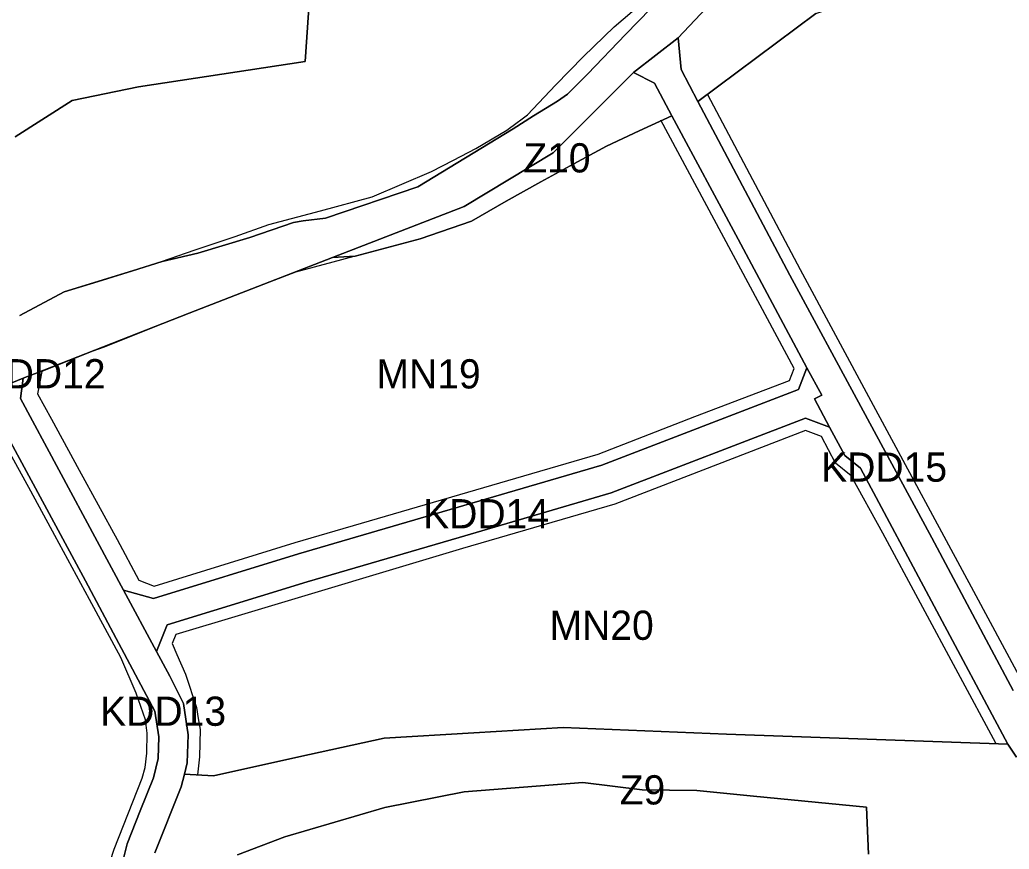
# Model space of a CAD drawing. Extents: x 7428841 to 7433518, y 5545054 to 5546840.
# Drawn here: x 7430323 to 7430661.7, y 5545549.4 to 5545833.3 of the extents above; entities that cross this region are included whole.
import ezdxf

# ---------------------------------------------------------------- set-up
doc = ezdxf.new("R2010")
doc.units = 0
for name, color, linetype in [('linie_rozgraniczajace', 7, 'Continuous'), ('linie_zabudowy_nieprzekraczalne', 7, 'Continuous'), ('oznaczenia_przeznaczen', 7, 'Continuous')]:
    doc.layers.add(name, color=color, linetype=linetype)

msp = doc.modelspace()

# ---------------------------------------------------------------- linework, layer by layer
at = {"layer": 'linie_rozgraniczajace'}
for points in [[(7430663.1, 5545603.69), (7430635.16, 5545655.99), (7430586.55, 5545745.89), (7430555.14, 5545805.32), (7430595.45, 5545835.45), (7430635.56, 5545849.06), (7430627.71, 5545865.6), (7430632.95, 5545868.01), (7430642.11, 5545873.01), (7430651.28, 5545878), (7430675.25, 5545892.35)], [(7430569.32, 5545849.46), (7430548.34, 5545827.05), (7430540.7, 5545821.15), (7430533.06, 5545815.25), (7430505.57, 5545787.69), (7430475.12, 5545769.42), (7430430.05, 5545751.94), (7430380.93, 5545732.82), (7430328.04, 5545712.13), (7430324.14, 5545710.6), (7430320.24, 5545709.08)], [(7430595.45, 5545835.45), (7430555.14, 5545805.32), (7430549.37, 5545816.25), (7430548.34, 5545827.05), (7430569.32, 5545849.46)], [(7430321.42, 5545793.16), (7430340.97, 5545805.64), (7430363.66, 5545810.3), (7430420.71, 5545819.01), (7430422.45, 5545844.1)], [(7430422.45, 5545844.1), (7430420.71, 5545819.01), (7430363.66, 5545810.3), (7430340.97, 5545805.64), (7430321.42, 5545793.16)], [(7430322.99, 5545732.04), (7430338.17, 5545740.16), (7430361.53, 5545747.33), (7430371.7, 5545750.49), (7430383.92, 5545753.38), (7430401.78, 5545758.72), (7430416.65, 5545763.91), (7430420.04, 5545764.49), (7430427.68, 5545765.38), (7430459.23, 5545776.13), (7430491.84, 5545795.96), (7430498.85, 5545800.42), (7430507.04, 5545805.4), (7430510.44, 5545807.79), (7430517.4, 5545814.73), (7430530.39, 5545828.27), (7430538.96, 5545837.09)], [(7430538.96, 5545837.09), (7430530.39, 5545828.27), (7430517.4, 5545814.73), (7430510.44, 5545807.79), (7430507.04, 5545805.4), (7430498.85, 5545800.42), (7430491.84, 5545795.96), (7430459.23, 5545776.13), (7430427.68, 5545765.38), (7430420.04, 5545764.49), (7430416.65, 5545763.91), (7430401.78, 5545758.72), (7430383.92, 5545753.38), (7430371.7, 5545750.49), (7430361.53, 5545747.33), (7430338.17, 5545740.16), (7430322.99, 5545732.04)], [(7430664.22, 5545580.93), (7430661.23, 5545585.41), (7430610.78, 5545679.77), (7430605.4, 5545684.16), (7430600.22, 5545693.85), (7430595.05, 5545703.55), (7430597.5, 5545704.75), (7430592.46, 5545714.16), (7430568.88, 5545758.14), (7430546.21, 5545800.44), (7430540.26, 5545811.53), (7430533.06, 5545815.25), (7430540.7, 5545821.15), (7430548.34, 5545827.05), (7430549.37, 5545816.25), (7430555.14, 5545805.32), (7430586.55, 5545745.89), (7430635.16, 5545655.99), (7430663.1, 5545603.69)], [(7430356.4, 5545538.02), (7430359.72, 5545551.27), (7430364.23, 5545562.59), (7430368.74, 5545573.91), (7430370.39, 5545580.44), (7430370.65, 5545587.94), (7430369.28, 5545596.66), (7430345.47, 5545641.25), (7430316.75, 5545694.49), (7430313.95, 5545699.78), (7430307.55, 5545703.17), (7430320.24, 5545709.08), (7430324.14, 5545710.6), (7430323.19, 5545703.65), (7430349.47, 5545654.88), (7430358.51, 5545638.06), (7430369.81, 5545617.05), (7430374.39, 5545608.67), (7430378.99, 5545599.31), (7430380.68, 5545588.55), (7430380.35, 5545579.03), (7430379.33, 5545575.09), (7430378.27, 5545570.82), (7430369.25, 5545548.19)], [(7430229.77, 5545546.84), (7430211.33, 5545566.73), (7430187.12, 5545592.88), (7430159.46, 5545623.96), (7430159.13, 5545632.06), (7430161.15, 5545634.58), (7430188, 5545647.19), (7430214.85, 5545659.79), (7430268.56, 5545685.01), (7430307.55, 5545703.17), (7430313.95, 5545699.78), (7430316.75, 5545694.49), (7430345.47, 5545641.25), (7430369.28, 5545596.66), (7430370.65, 5545587.94), (7430370.39, 5545580.44), (7430368.74, 5545573.91), (7430364.23, 5545562.59), (7430359.72, 5545551.27), (7430356.4, 5545538.02)], [(7430369.25, 5545548.19), (7430378.27, 5545570.82), (7430379.33, 5545575.09), (7430389.29, 5545574.54), (7430418.51, 5545581), (7430447.74, 5545587.45), (7430478.37, 5545589.24), (7430509.01, 5545591.03), (7430564.93, 5545588.74), (7430661.23, 5545585.41), (7430664.22, 5545580.93)], [(7430397.54, 5545547.49), (7430413.69, 5545553.71), (7430447.96, 5545563.72), (7430475.07, 5545569.11), (7430495.4, 5545570.66), (7430515.74, 5545572.22), (7430525.89, 5545570.98), (7430536.05, 5545569.74), (7430545.4, 5545569.61), (7430554.75, 5545569.48), (7430574.15, 5545567.59), (7430612.89, 5545563.81), (7430613.58, 5545547.7)], [(7430613.58, 5545547.7), (7430612.89, 5545563.81), (7430574.15, 5545567.59), (7430554.75, 5545569.48), (7430545.4, 5545569.61), (7430536.05, 5545569.74), (7430525.89, 5545570.98), (7430515.74, 5545572.22), (7430495.4, 5545570.66), (7430475.07, 5545569.11), (7430447.96, 5545563.72), (7430413.69, 5545553.71), (7430397.54, 5545547.49)]]:
    msp.add_lwpolyline(points, dxfattribs=at)
for points in [[(7430430.05, 5545751.94), (7430475.12, 5545769.42), (7430505.57, 5545787.69), (7430533.06, 5545815.25), (7430540.26, 5545811.53), (7430546.21, 5545800.44), (7430535.05, 5545795.23), (7430523.89, 5545790.02), (7430512.61, 5545783.93), (7430501.32, 5545777.84), (7430489.53, 5545771.19), (7430477.62, 5545764.37), (7430460.11, 5545758.29), (7430437.82, 5545752.38)], [(7430323.19, 5545703.65), (7430324.14, 5545710.6), (7430328.04, 5545712.13), (7430380.93, 5545732.82), (7430430.05, 5545751.94), (7430437.82, 5545752.38), (7430460.11, 5545758.29), (7430477.62, 5545764.37), (7430489.53, 5545771.19), (7430501.32, 5545777.84), (7430512.61, 5545783.93), (7430523.89, 5545790.02), (7430535.05, 5545795.23), (7430546.21, 5545800.44), (7430568.88, 5545758.14), (7430592.46, 5545714.16), (7430589.53, 5545706.78), (7430522.26, 5545680.81), (7430470.35, 5545665.66), (7430418.45, 5545650.52), (7430368.81, 5545635.24), (7430358.51, 5545638.06), (7430349.47, 5545654.88)], [(7430358.51, 5545638.06), (7430368.81, 5545635.24), (7430418.45, 5545650.52), (7430470.35, 5545665.66), (7430522.26, 5545680.81), (7430589.53, 5545706.78), (7430592.46, 5545714.16), (7430597.5, 5545704.75), (7430595.05, 5545703.55), (7430600.22, 5545693.85), (7430591.94, 5545696.99), (7430525.47, 5545671.33), (7430473.39, 5545656.13), (7430421.32, 5545640.94), (7430373.44, 5545626.2), (7430369.81, 5545617.05)], [(7430369.81, 5545617.05), (7430373.44, 5545626.2), (7430421.32, 5545640.94), (7430473.39, 5545656.13), (7430525.47, 5545671.33), (7430591.94, 5545696.99), (7430600.22, 5545693.85), (7430605.4, 5545684.16), (7430610.78, 5545679.77), (7430661.23, 5545585.41), (7430564.93, 5545588.74), (7430509.01, 5545591.03), (7430478.37, 5545589.24), (7430447.74, 5545587.45), (7430418.51, 5545581), (7430389.29, 5545574.54), (7430379.33, 5545575.09), (7430380.35, 5545579.03), (7430380.68, 5545588.55), (7430378.99, 5545599.31), (7430374.39, 5545608.67)]]:
    msp.add_lwpolyline(points, close=True, dxfattribs=at)
at = {"layer": 'linie_zabudowy_nieprzekraczalne'}
for points in [[(7430322.99, 5545732.04), (7430338.17, 5545740.16), (7430349.85, 5545743.75), (7430361.53, 5545747.33), (7430371.52, 5545750.51), (7430383.04, 5545754.49), (7430396.69, 5545759.12), (7430408.25, 5545763.16), (7430425.96, 5545767.9), (7430443.67, 5545772.63), (7430463.9, 5545781.4), (7430471.51, 5545785.28), (7430479.11, 5545789.16), (7430489.75, 5545795.47), (7430493.25, 5545798.12), (7430494.48, 5545799.04), (7430496.78, 5545800.75), (7430506.43, 5545810.85), (7430515.94, 5545820.7), (7430526.43, 5545830.89), (7430538.8, 5545841.5), (7430541.3, 5545843.63), (7430544.56, 5545846.49)], [(7430558.4, 5545807.72), (7430590.08, 5545747.77), (7430614.37, 5545702.84), (7430650.25, 5545636.23), (7430669.09, 5545601.23), (7430677.86, 5545585.93)], [(7430588.05, 5545713.92), (7430542.48, 5545798.92)], [(7430437.4, 5545752.23), (7430430.11, 5545750.3), (7430417.35, 5545746.94), (7430405.49, 5545742.38), (7430380.93, 5545732.82), (7430351.5, 5545721.08), (7430348.01, 5545719.91), (7430330.83, 5545713.03)], [(7430330.53, 5545712.91), (7430329.08, 5545705.25), (7430333.85, 5545696.57), (7430343.31, 5545679.1), (7430356.38, 5545655.43), (7430363.76, 5545641.51)], [(7430363.76, 5545641.51), (7430368.97, 5545639.47), (7430417.3, 5545654.35), (7430520.97, 5545684.6), (7430554.1, 5545697.46), (7430586.46, 5545709.88), (7430588.05, 5545713.92)], [(7430352.62, 5545523.31), (7430351.71, 5545527.21), (7430351.75, 5545535.04), (7430352.52, 5545541), (7430355.29, 5545549.4), (7430364.94, 5545573.76), (7430365.95, 5545577.43), (7430366.53, 5545582.28), (7430366.66, 5545589.17), (7430365.98, 5545593.7), (7430362.88, 5545602.83), (7430357.63, 5545614.99), (7430346.86, 5545634.84), (7430334.97, 5545656.8), (7430326.8, 5545671.95), (7430319.76, 5545684.81), (7430313.72, 5545695.75), (7430303.88, 5545701.34)], [(7430597.39, 5545690.67), (7430591.95, 5545692.71), (7430526.75, 5545667.54), (7430474.53, 5545652.3), (7430398.94, 5545629.66), (7430376.45, 5545622.92), (7430375.18, 5545619.8)], [(7430657.1, 5545585.71), (7430618.4, 5545657.59), (7430607.65, 5545677.16), (7430602.25, 5545681.56), (7430597.39, 5545690.67)], [(7430375.18, 5545619.8), (7430376.76, 5545616.08), (7430379.69, 5545609.3), (7430383.54, 5545597.97), (7430384.11, 5545594.16), (7430384.69, 5545590.35), (7430384.51, 5545581.02), (7430383.78, 5545574.87)]]:
    msp.add_lwpolyline(points, dxfattribs=at)

# ---------------------------------------------------------------- texts
at = {"layer": 'oznaczenia_przeznaczen'}
for s, p in [('Z10', (7430495.34, 5545781.02)), ('KDD12', (7430309.26, 5545707.13)), ('MN19', (7430445.1, 5545707.1)), ('KDD15', (7430597.33, 5545675.19)), ('KDD14', (7430461.08, 5545659.23)), ('MN20', (7430504.35, 5545621.07)), ('KDD13', (7430350.51, 5545591.66)), ('Z9', (7430528.36, 5545564.74))]:
    msp.add_text(s, height=10, dxfattribs=at).set_placement(p)

doc.saveas('drawing.dxf')
